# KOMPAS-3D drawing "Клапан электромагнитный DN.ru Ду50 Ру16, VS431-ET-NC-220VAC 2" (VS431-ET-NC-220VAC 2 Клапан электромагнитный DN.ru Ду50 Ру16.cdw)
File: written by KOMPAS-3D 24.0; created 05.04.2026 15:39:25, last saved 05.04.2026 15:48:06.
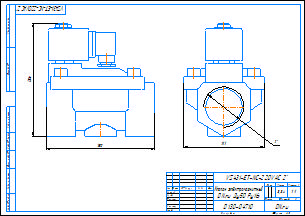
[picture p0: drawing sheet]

Document properties: c3d_UniqueCompID: ef56311e-7521-43dc-8291-0e6108b3d81d; Автор: artio; Класс точности: c; Знак неуказанной шероховатости: Шероховатость не задана; Рассекать на разрезах: Да; c3d_UniqueCompID: ef56311e-7521-43dc-8291-0e6108b3d81d; Автор: artio; Класс точности: c; Знак неуказанной шероховатости: Шероховатость не задана; Рассекать на разрезах: Да; c3d_UniqueCompID: ef56311e-7521-43dc-8291-0e6108b3d81d; Автор: artio; Класс точности: c; Знак неуказанной шероховатости: Шероховатость не задана; Рассекать на разрезах: Да; c3d_UniqueCompID: ef56311e-7521-43dc-8291-0e6108b3d81d; Автор: artio; Класс точности: c; Знак неуказанной шероховатости: Шероховатость не задана; Рассекать на разрезах: Да; c3d_UniqueCompID: ef56311e-7521-43dc-8291-0e6108b3d81d; Автор: artio; Класс точности: c; Знак неуказанной шероховатости: Шероховатость не задана; Рассекать на разрезах: Да; Автор: artio; Форматы листов документа: A3; Полное имя файла: VS431-ET-NC-220VAC 2 Клапан электромагнитный DN.ru Ду50 Ру16.m3d; Масса: 3.341; Наименование: Клапан электромагнитный DN.ru Ду50 Ру16; Количество листов документа: 1; Примечание: D130-04710

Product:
- Body: Тело 1  | qty 1
    Масса: 6.703651
- Part/product: Клапан электромагнитный DN.ru Ду50 Ру16  | designation VS431-ET-NC-220VAC 2
    Масса: 3.341
    Раздел спецификации: Прочие изделия
    Примечание: D130-04710
    additional columns: ef56311e-7521-43dc-8291-0e6108b3d81d; artio; c; Шероховатость не задана; Да

Views: Вид 1, Спереди
Referenced files in C:\Users\artio\OneDrive\Рабочий стол\Клапан электромагнитный DN.ru\VS431\VS431-ET-NC\: VS431-ET-NC-220VAC 3-4 Клапан электромагнитный DN.ru Ду20 Ру16.m3d, VS431-ET-NC-220VAC 2 Клапан электромагнитный DN.ru Ду50 Ру16.m3d, VS431-ET-NC-220VAC 3-4 Клапан электромагнитный DN.ru Ду20 Ру16.cdw
Referenced files in C:\Users\artio\OneDrive\Рабочий стол\Клапан электромагнитный DN.ru\VS431\VS431-ET-NC\VS431-ET-NC-220VAC\Ду50\: VS431-ET-NC-220VAC 2 Клапан электромагнитный DN.ru Ду50 Ру16.m3d
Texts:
  VS431-ET-NC-220VAC 2
  Клапан электромагнитный
  DN.ru Ду50 Ру16
  VS431-ET-NC-220VAC 2"
  VS431-ET-NC-220VAC 2"-
  Клапан электромагнитный DN.ru Ду50 Ру16
  VS431-ET-NC-220VAC 2 Клапан электромагнитный DN.ru Ду50 Ру16
Dimensions and other numbers on the sheet: 0; 3; 2; 4; 111; 1:1; 1; 3,34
